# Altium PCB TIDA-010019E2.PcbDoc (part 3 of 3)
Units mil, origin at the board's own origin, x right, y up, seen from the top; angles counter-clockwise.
Board outline 3159.64 x 4813.18 mil, 2 copper layers (Top Layer, Bottom Layer), stack 62 mil thick; 303 components, 177 nets, 861 pads, 1443 vias.
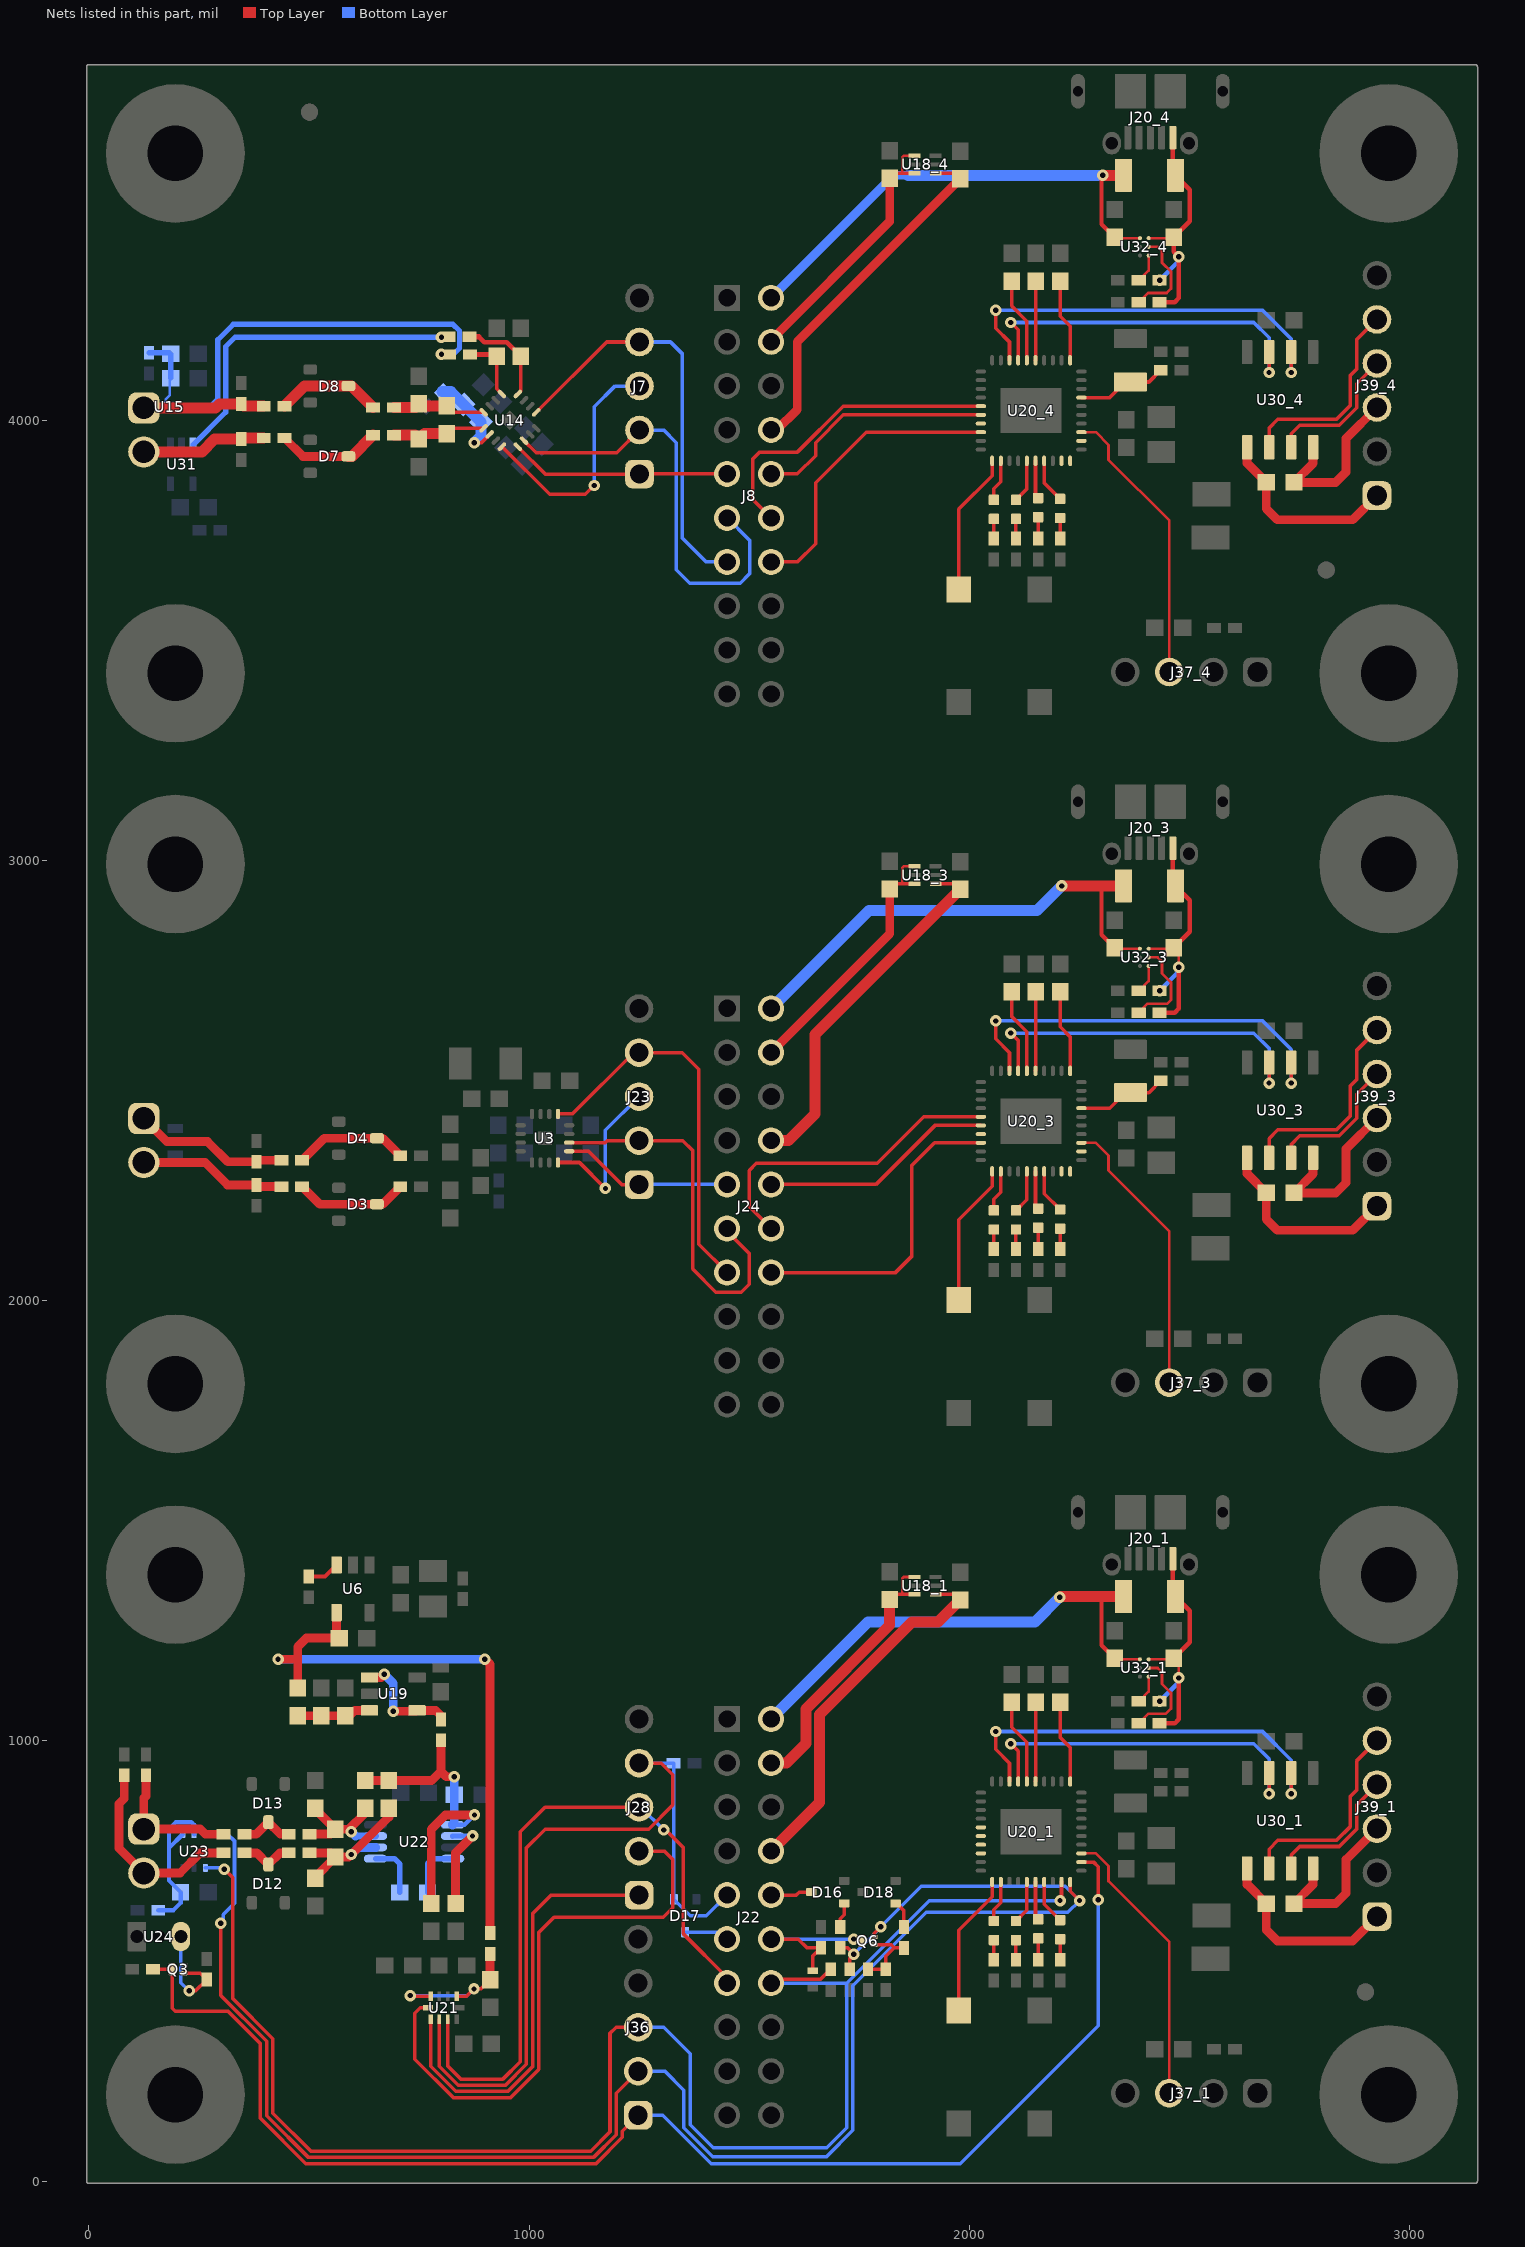
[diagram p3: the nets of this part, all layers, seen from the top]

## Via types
v1: diameter 28, hole 12, Top Layer to Bottom Layer, tented both sides, 1305 vias
v2: diameter 26, hole 12, Top Layer to Bottom Layer, tented both sides, 120 vias
v3: diameter 19.68, hole 7.87, Top Layer to Bottom Layer, tented both sides, 17 vias
v4: diameter 26, hole 12, Top Layer to Bottom Layer, 1 vias

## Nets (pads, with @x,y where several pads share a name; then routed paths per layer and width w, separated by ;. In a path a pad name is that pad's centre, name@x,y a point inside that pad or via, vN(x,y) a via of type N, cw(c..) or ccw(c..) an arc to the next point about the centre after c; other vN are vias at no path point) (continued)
NetC23_3_1: C23_3.1 U20_3.7 Y1_3.1 | length 206
  Top Layer w8: U20_3.7@2254.88,2437.64 2318.89,2437.64 2354.18,2472.93 Y1_3.1@2366.22,2472.93 2408.28,2472.93 C23_3.1@2435.12,2499.77
NetC23_4_1: C23_4.1 U20_4.7 Y1_4.1 | length 206
  Top Layer w8: U20_4.7@2254.88,4051.81 2318.88,4051.81 2354.17,4087.1 Y1_4.1@2366.21,4087.1 2408.27,4087.1 C23_4.1@2435.11,4113.94
NetC34_1_1: C34_1.1 F1_1.2 J20_1.1 R116_1.2 R117_1.2 U32_1.A2 | length 556.1
  Top Layer w6: U32_1.A2@2407.56,1185.53 C34_1.1@2462.47,1185.53 ; C34_1.1@2464.55,1187.61 2476.22,1175.94 v2(2476.22,1143.21)
  Top Layer w10: R116_1.2@2432.65,1040 2466.61,1040 2476.22,1049.61 v2(2476.22,1143.21) ; F1_1.2@2462.68,1334.2 J20_1.1@2462.68,1414.06 ; C34_1.1@2464.55,1187.61 2501.11,1224.17 2501.11,1295.77 F1_1.2@2468.58,1328.3
  Bottom Layer w10: v2(2432.65,1090) v2@2476.22,1133.57
NetC34_3_1: C34_3.1 F1_3.2 J20_3.1 R116_3.2 R117_3.2 U32_3.A2 | length 556.1
  Top Layer w6: U32_3.A2@2407.56,2799.7 C34_3.1@2462.47,2799.7 ; C34_3.1@2464.55,2801.78 2476.22,2790.11 v2(2476.22,2757.38)
  Top Layer w10: R116_3.2@2432.65,2654.17 2466.61,2654.17 2476.22,2663.78 v2(2476.22,2757.38) ; F1_3.2@2462.68,2948.37 J20_3.1@2462.68,3028.24 ; C34_3.1@2464.55,2801.78 2501.11,2838.34 2501.11,2909.94 F1_3.2@2468.58,2942.47
  Bottom Layer w10: v2(2432.65,2704.17) v2@2476.22,2747.74
NetC34_4_1: C34_4.1 F1_4.2 J20_4.1 R116_4.2 R117_4.2 U32_4.A2 | length 577
  Top Layer w6: U32_4.A2@2407.55,4413.87 2462.46,4413.87 C34_4.1@2464.54,4415.95
  Top Layer w10: R116_4.2@2432.65,4268.34 2466.61,4268.34 2476.21,4277.95 v2(2476.21,4371.55) 2464.54,4383.22 C34_4.1@2464.54,4415.95 2501.1,4452.51 2501.1,4524.11 F1_4.2@2468.58,4556.64 2462.67,4562.54 J20_4.1@2462.67,4642.4
  Bottom Layer w10: v2(2432.65,4318.34) 2476.21,4361.91 v2(2476.21,4371.55)
NetC37_1: C37.1 C42.1 R47.1 U14.9 | length 217.6
  Top Layer w8: C42.1@813.43,3969.85 825.48,3981.9 U14.9@896.79,3981.9
  Top Layer w25: R47.1@692.9,3966.39 741.15,3966.39 C37.1@749.99,3957.54 762.29,3969.85 C42.1@813.43,3969.85
NetC40_1: C40.1 C41.1 R44.1 U14.10 | length 212.8
  Top Layer w8: v2(875.79,3949.36) 892.09,3949.36 U14.10@910.71,3967.99
  Bottom Layer w25: R44.1@802.86,4065.04 822.74,4065.04 C41.1@891.1,3996.67 891.1,3964.67 v2(875.79,3949.36)
NetC42_2: C42.2 C43.1 R49.1 U14.8 | length 211.5
  Top Layer w8: C42.2@813.43,4032.84 828.17,4018.1 U14.8@896.79,4018.1
  Top Layer w25: R49.1@692.9,4029.23 741.85,4029.23 745.46,4032.84 C42.2@813.43,4032.84
NetC44_1: C44.1 C45.1 R50.1 U15.A2 U15.B2 | length 182.9
  Bottom Layer w6: U15.B2@175.02,4022.79 U15.A2@175.02,4038.54 175.02,4048.19 183.51,4056.68 183.51,4093.63 C45.1@186.02,4096.13
  Bottom Layer w12: R50.1@136.85,4153.51 183.43,4153.51 C44.1@186.02,4150.92 C45.1@186.02,4096.13
NetC46_1: C46.1 R52.1 U14.5 | length 153.9
  Top Layer w8: C46.1@926.81,4145.99 926.59,4145.77 926.59,4071.81 U14.5@938.55,4059.85
  Top Layer w12: R52.1@865.59,4149.63 923.17,4149.63 C46.1@926.81,4145.99
NetC53_1: C53.1 R8.1 R72.2 U19.3 | length 167.7
  Top Layer w20: R8.1@474.83,1057.29 C53.1@582.92,1057.29 591.78,1057.29 603.95,1069.47 U19.3@637.52,1069.47
NetC67_1: C67.1 R70.1 U21.1 U21.4 | length 347.1
  Top Layer w8: v2(730.54,421.63) 731.52,420.65 U21.4@776.51,420.65 ; U21.1@835.56,420.65 858.98,420.65 v2(875.09,436.76) 890.38,436.76 C67.1@911.54,457.91
  Top Layer w20: C67.1@911.54,457.91 R70.1@911.54,516.37
  Bottom Layer w8: v2(730.54,421.63) 859.97,421.63 v2(875.09,436.76)
NetC69_2: C69.2 C70.1 R74.1 R77.1 U22.2 | length 370.3
  Top Layer w20: R77.1@501.53,745.83 550.56,745.83 C70.1@560,736.39 ; C69.2@514.06,688.28 514.06,690.45 C70.1@560,736.39 ; R74.1@681.81,847.24 681.81,827.6 v2(596.33,742.13) 590.6,736.39 C70.1@560,736.39
  Bottom Layer w20: v2(596.33,742.13) 612.53,758.32 U22.2@651.21,758.32
NetC70_2: C70.2 C73.1 R75.1 R82.1 U22.3 | length 282.9
  Top Layer w20: R82.1@501.53,788.39 549,788.39 C70.2@560,799.38 ; C73.1@514.06,847.24 514.06,845.32 C70.2@560,799.38 ; R75.1@628,847.24 628,836.49 590.89,799.38 C70.2@560,799.38
  Bottom Layer w16: 605.95,784.32 U22.3@651.21,784.32
  Bottom Layer w20: v2(596.33,793.94) 605.95,784.32
NetC72_1: C72.1 R71.1 R74.2 R75.2 R80.1 U22.5 | length 729.7
  Top Layer w20: R75.2@628,910.23 R74.2@681.81,910.23 779.17,910.23 800,931.07 ; R80.1@778,630.81 778,799.52 810.56,832.08 v2(876.15,832.08) ; R71.1@800,993.94 800,931.07 ; v2(830.24,918.7) 812.37,918.7 800,931.07
  Bottom Layer w10: U22.5@826.41,809.51 853.57,809.51 v2(876.15,832.08)
  Bottom Layer w20: U22.5@826.41,809.51 825.72,810.19 830.24,814.71 C72.1@830.24,877.53 v2(830.24,918.7)
NetC74_1: C74.1 R85.2 U23.4 U23.5 | length 368.4
  Bottom Layer w10: R85.2@157.78,615.83 192.31,615.83 208.5,632.02 C74.1@208.5,656.78 182.09,683.2 182.09,756.81 ; U23.4@213.66,788.39 182.09,756.81 ; U23.5@239.25,788.39 239.25,809.44 232.87,815.83 197.91,815.83 182.09,800 182.09,756.81
NetC83_1_1: C83_1.1 J22.4 U18_1.4 U18_1.6 | length 630.9
  Top Layer w6: 1846.22,1333.22 1847.99,1334.99 1847.99,1369.38 1851.2,1372.59 U18_1.4@1875.83,1372.59
  Top Layer w8: C83_1.1@1819.45,1321.41 1831.26,1333.22 1846.22,1333.22 U18_1.6@1875.83,1333.22
  Top Layer w25: J22.4@1550,950 1585.06,950 1629,993.94 1629,1072.84 1819.45,1263.29 C83_1.1@1819.45,1321.41
NetC83_3_1: C83_3.1 J24.4 U18_3.4 U18_3.6 | length 610.3
  Top Layer w6: 1846.22,2947.39 1847.99,2949.16 1847.99,2983.55 1851.2,2986.76 U18_3.4@1875.83,2986.76
  Top Layer w8: C83_3.1@1819.45,2935.58 1831.26,2947.39 1846.22,2947.39 U18_3.6@1875.83,2947.39
  Top Layer w20: J24.4@1550,2564.17 1819.45,2833.62 C83_3.1@1819.45,2935.58
NetC83_4_1: C83_4.1 J8.4 U18_4.4 U18_4.6 | length 610.3
  Top Layer w6: 1846.21,4561.56 1847.99,4563.33 1847.99,4597.72 1851.19,4600.93 U18_4.4@1875.82,4600.93
  Top Layer w8: C83_4.1@1819.44,4549.75 1831.25,4561.56 1846.21,4561.56 U18_4.6@1875.82,4561.56
  Top Layer w20: v4(1550,4182.5) 1819.44,4451.95 C83_4.1@1819.44,4549.75
  Bottom Layer w20: J8.4@1550,4178.35 v4(1550,4182.5)
NetC84_1_1: C84_1.1 J22.8 U18_1.1 | length 843.8
  Top Layer w8: U18_1.1@1923.86,1333.22 1966.54,1333.22 C84_1.1@1979.45,1320.31
  Top Layer w25: J22.8@1550,750 1660,860 1660,1060 1870,1270 1929.14,1270 C84_1.1@1979.45,1320.31
NetC84_3_1: C84_3.1 J24.8 U18_3.1 | length 832.4
  Top Layer w8: U18_3.1@1923.86,2947.39 1966.54,2947.39 C84_3.1@1979.45,2934.48
  Top Layer w25: J24.8@1550,2364.17 1589.81,2364.17 1650,2424.37 1650,2605.03 C84_3.1@1979.45,2934.48
NetC84_4_1: C84_4.1 J8.8 U18_4.1 | length 816.8
  Top Layer w8: U18_4.1@1923.85,4561.56 1966.53,4561.56 C84_4.1@1979.44,4548.65
  Top Layer w20: J8.8@1563.19,3978.35 1609.14,4024.3 1609.14,4178.35 C84_4.1@1979.44,4548.65
  Top Layer w25: J8.8@1550,3978.35 J8.8@1563.19,3978.35
NetC85_1_1: C85_1.1 J39_1.1 U30_1.5 | length 442.3
  Top Layer w20: U30_1.5@2631.22,710.54 2631.22,674.3 C85_1.1@2674.72,630.8 2674.72,570.87 2699.7,545.9 2871.23,545.9 J39_1.1@2926.22,600.89
NetC85_1_2: C85_1.2 J39_1.3 U30_1.8 | length 401.4
  Top Layer w20: U30_1.8@2781.22,710.54 2781.22,674.3 C85_1.2@2737.72,630.8 2832.38,630.8 2856.22,654.64 2856.22,730.89 J39_1.3@2926.22,800.89
NetC85_3_1: C85_3.1 J39_3.1 U30_3.5 | length 442.3
  Top Layer w20: U30_3.5@2631.22,2324.71 2631.22,2288.48 C85_3.1@2674.72,2244.97 2674.72,2185.05 2699.7,2160.07 2871.23,2160.07 J39_3.1@2926.22,2215.06
NetC85_3_2: C85_3.2 J39_3.3 U30_3.8 | length 401.4
  Top Layer w20: U30_3.8@2781.22,2324.71 2781.22,2288.48 C85_3.2@2737.72,2244.97 2832.38,2244.97 2856.22,2268.82 2856.22,2345.06 J39_3.3@2926.22,2415.06
NetC85_4_1: C85_4.1 J39_4.1 U30_4.5 | length 442.3
  Top Layer w20: U30_4.5@2631.21,3938.88 2631.21,3902.65 C85_4.1@2674.72,3859.14 2674.72,3799.22 2699.69,3774.24 2871.22,3774.24 J39_4.1@2926.21,3829.23
NetC85_4_2: C85_4.2 J39_4.3 U30_4.8 | length 401.4
  Top Layer w20: U30_4.8@2781.21,3938.88 2781.21,3902.65 C85_4.2@2737.71,3859.14 2832.37,3859.14 2856.21,3882.98 2856.21,3959.23 J39_4.3@2926.21,4029.23
NetC87_2: C87.2 Q6.1 R110.1 R115.2 | length 168.4
  Top Layer w8: R110.1@1770,481.54 C87.2@1810.76,481.54 1810.76,511.04 1829.87,530.15 ; Q6.1@1783.52,537.04 1822.98,537.04 1829.87,530.15 ; R115.2@1851.76,530.15 1829.87,530.15
NetC88_1: C88.1 J22.12 Q6.3 R84.1 | length 369
  Top Layer w8: J22.12@1550,550 1611.72,550 1631.4,530.32 C88.1@1663.35,530.32 1645,511.97 R84.1@1645,477.91
  Bottom Layer w8: J22.12@1550,550 v2(1737.46,550)
NetC89_1_1: C89_1.1 F1_1.1 J22.2 U32_1.A1 | length 1125.9
  Top Layer w6: C89_1.1@2332.36,1185.53 U32_1.A1@2387.87,1185.53
  Top Layer w10: 2304.51,1328.3 2300.58,1324.36 2300.58,1217.31 C89_1.1@2330.28,1187.61
  Top Layer w25: v2(2205.5,1326.49) 2207.31,1328.3 2304.51,1328.3 F1_1.1@2350.47,1328.3
  Bottom Layer w25: J22.2@1550,1050 1770,1270 2149.01,1270 v2(2205.5,1326.49)
NetC89_3_1: C89_3.1 F1_3.1 J24.2 U32_3.A1 | length 1124.5
  Top Layer w6: C89_3.1@2332.36,2799.7 U32_3.A1@2387.87,2799.7
  Top Layer w10: 2300,2942.47 2300.58,2941.89 2300.58,2831.48 C89_3.1@2330.28,2801.78
  Top Layer w25: v2(2210,2942.46) 2300,2942.47 F1_3.1@2350.47,2942.47
  Bottom Layer w25: J24.2@1550,2664.17 1772.49,2886.67 2154.2,2886.67 v2(2210,2942.46)
NetC89_4_1: C89_4.1 F1_4.1 J8.2 U32_4.A1 | length 1134.7
  Top Layer w6: C89_4.1@2330.28,4415.95 2332.36,4413.87 U32_4.A1@2387.87,4413.87
  Top Layer w10: v2(2303.59,4556.64) 2300.57,4553.62 2300.57,4445.65 C89_4.1@2330.28,4415.95
  Top Layer w25: v2(2303.59,4556.64) 2339.35,4556.64 F1_4.1@2351.68,4544.31
  Bottom Layer w20: J8.2@1550,4278.35 1828.29,4556.64 1861.02,4556.64
  Bottom Layer w25: 1861.02,4556.64 v2(2303.59,4556.64)
NetC90_1: C90.1 R121.1 U14.4 | length 223.3
  Top Layer w8: U14.4@974.74,4059.85 981.02,4066.14 C90.1@981.02,4145.99
  Top Layer w10: 885.75,4190 898.27,4177.48 949.53,4177.48 C90.1@981.02,4145.99
  Top Layer w12: R121.1@864.65,4190 885.75,4190
NetD1_1_1: D1_1.1 R27_1.2 | length 46.6
  Top Layer w8: R27_1.2@2206.46,503.19 D1_1.1@2206.46,549.83
NetD1_1_2: D1_1.2 U20_1.37 | length 101.6
  Top Layer w8: U20_1.37@2170.24,679.77 2170.24,629.36 D1_1.2@2206.46,593.14
NetD1_3_1: D1_3.1 R27_3.2 | length 46.6
  Top Layer w8: R27_3.2@2206.46,2117.36 D1_3.1@2206.46,2164.01
NetD1_3_2: D1_3.2 U20_3.37 | length 101.6
  Top Layer w8: U20_3.37@2170.24,2293.94 2170.24,2243.54 D1_3.2@2206.46,2207.32
NetD1_4_1: D1_4.1 R27_4.2 | length 46.6
  Top Layer w8: R27_4.2@2206.45,3731.53 D1_4.1@2206.45,3778.18
NetD1_4_2: D1_4.2 U20_4.37 | length 101.6
  Top Layer w8: U20_4.37@2170.23,3908.11 2170.23,3857.7 D1_4.2@2206.45,3821.48
NetD2_1_1: D2_1.1 R55_1.2 | length 48.6
  Top Layer w8: R55_1.2@2156.46,503.19 D2_1.1@2156.46,551.8
NetD2_1_2: D2_1.2 U20_1.36 | length 87.1
  Top Layer w8: U20_1.36@2150.55,679.77 2150.55,601.02 D2_1.2@2156.46,595.11
NetD2_3_1: D2_3.1 R55_3.2 | length 48.6
  Top Layer w8: R55_3.2@2156.46,2117.36 D2_3.1@2156.46,2165.98
NetD2_3_2: D2_3.2 U20_3.36 | length 87.1
  Top Layer w8: U20_3.36@2150.55,2293.94 2150.55,2215.19 D2_3.2@2156.46,2209.28
NetD2_4_1: D2_4.1 R55_4.2 | length 48.6
  Top Layer w8: R55_4.2@2156.45,3731.53 D2_4.1@2156.45,3780.15
NetD2_4_2: D2_4.2 U20_4.36 | length 87.1
  Top Layer w8: U20_4.36@2150.54,3908.11 2150.54,3829.36 D2_4.2@2156.45,3823.45
NetD3_3: D3.3 R11.1 R12.2 | length 255.9
  Top Layer w20: R11.1@484.68,2259.41 524.68,2219.41 D3.3@654.37,2219.41 667.44,2219.41 R12.2@707.44,2259.41
NetD4_3: D4.3 R13.1 R14.2 | length 260
  Top Layer w20: R13.1@484.68,2319.41 534.68,2369.41 D4.3@654.37,2369.41 667.44,2369.41 R14.2@707.44,2329.41
NetD7_3: D7.3 R46.1 R47.2 | length 238.3
  Top Layer w20: R46.1@444.65,3960 486.49,3918.16 D7.3@589.72,3918.16
  Top Layer w25: D7.3@589.72,3918.16 597.43,3918.16 R47.2@645.66,3966.39
NetD8_3: D8.3 R48.1 R49.2 | length 240.4
  Top Layer w25: R48.1@444.65,4032.13 444.65,4032.4 490.25,4078 D8.3@589.72,4078 596.89,4078 R49.2@645.66,4029.23
NetD9_1_1: D9_1.1 R56_1.2 | length 44.5
  Top Layer w8: R56_1.2@2106.22,503.19 D9_1.1@2106.22,547.72
NetD9_1_2: D9_1.2 U20_1.35 | length 98.9
  Top Layer w8: D9_1.2@2106.22,591.03 2130.87,615.68 U20_1.35@2130.87,679.77
NetD9_3_1: D9_3.1 R56_3.2 | length 44.5
  Top Layer w8: R56_3.2@2106.22,2117.36 D9_3.1@2106.22,2161.9
NetD9_3_2: D9_3.2 U20_3.35 | length 98.9
  Top Layer w8: D9_3.2@2106.22,2205.2 2130.87,2229.85 U20_3.35@2130.87,2293.94
NetD9_4_1: D9_4.1 R56_4.2 | length 44.5
  Top Layer w8: R56_4.2@2106.21,3731.53 D9_4.1@2106.21,3776.07
NetD9_4_2: D9_4.2 U20_4.35 | length 98.9
  Top Layer w8: D9_4.2@2106.21,3819.37 2130.86,3844.02 U20_4.35@2130.86,3908.11
NetD10_1_1: D10_1.1 R57_1.2 | length 44.5
  Top Layer w8: R57_1.2@2056.06,503.19 D10_1.1@2056.06,547.72
NetD10_1_2: D10_1.2 U20_1.32 | length 95.3
  Top Layer w8: D10_1.2@2056.06,591.03 2056.06,616.56 2071.81,632.31 U20_1.32@2071.81,679.77
NetD10_3_1: D10_3.1 R57_3.2 | length 44.5
  Top Layer w8: R57_3.2@2056.06,2117.36 D10_3.1@2056.06,2161.9
NetD10_3_2: D10_3.2 U20_3.32 | length 95.3
  Top Layer w8: D10_3.2@2056.06,2205.2 2056.06,2230.73 2071.81,2246.48 U20_3.32@2071.81,2293.94
NetD10_4_1: D10_4.1 R57_4.2 | length 44.5
  Top Layer w8: R57_4.2@2056.06,3731.53 D10_4.1@2056.06,3776.07
NetD10_4_2: D10_4.2 U20_4.32 | length 95.3
  Top Layer w8: D10_4.2@2056.06,3819.37 2056.06,3844.9 2071.8,3860.65 U20_4.32@2071.8,3908.11
NetD12_3: D12.3 R76.1 R77.2 | length 122.6
  Top Layer w20: R76.1@353.62,745.83 381.46,745.83 D12.3@408,719.29 434.54,745.83 R77.2@454.29,745.83
NetD13_3: D13.3 R81.1 R82.2 | length 123.5
  Top Layer w20: R81.1@353.62,787.99 380.25,787.99 D13.3@408,815.74 435.36,788.39 R82.2@454.29,788.39
NetD16_1: D16.1 R114.1 | length 57.5
  Top Layer w8: R114.1@1706.65,577.57 1706.65,595.86 1716.24,605.45 D16.1@1716.24,631.14
NetD16_3: D16.3 J22.10 | length 94.2
  Top Layer w8: J22.10@1550,650 1607.1,650 1613.83,656.73 D16.3@1641.44,656.73
NetD18_1: D18.1 R115.1 | length 63.2
  Top Layer w8: D18.1@1832.67,631.14 1835.23,631.14 1851.76,614.61 R115.1@1851.76,577.39
NetJ2_1: J2.1 R13.2 R15.2 | length 354.7
  Top Layer w20: J2.1@125,2414.17 177.63,2361.55 269.67,2361.55 315.43,2315.78 R15.2@381.06,2315.78 384.68,2319.41 R13.2@437.44,2319.41
NetJ2_2: J2.2 R10.1 R11.2 | length 335.1
  Top Layer w20: J2.2@125,2314.17 264.14,2314.17 315.29,2263.03 R10.1@381.06,2263.03 384.68,2259.41 R11.2@437.44,2259.41
NetJ5_1: J5.1 R48.2 R51.2 | length 278.3
  Top Layer w25: J5.1@124.99,4028.35 287.55,4028.35 296.56,4037.36 R51.2@346.01,4037.36 351.24,4032.13 R48.2@397.4,4032.13
NetJ5_2: J5.2 R45.1 R46.2 | length 285.5
  Top Layer w25: J5.2@124.99,3928.35 256.85,3928.35 285.83,3957.33 R45.1@346.01,3957.33 348.69,3960 R46.2@397.4,3960
NetJ7_1: J7.1 J8.9 U14.13 | length 501.1
  Top Layer w8: U14.13@974.74,3940.15 1036.89,3878 J7.1@1251.02,3878 1251.37,3878.35 J8.9@1450,3878.35
NetJ7_2: J7.2 J8.11 U14.14 | length 1015.9
  Top Layer w8: U14.14@988.66,3954.07 1016.68,3926.05 1199.07,3926.05 J7.2@1251.02,3978
  Bottom Layer w8: J7.2@1251.02,3978 1305.98,3978 1334.52,3949.45 1334.52,3660.42 1364.95,3630 1479.6,3630 1501.02,3651.42 1501.02,3727.32 J8.11@1450,3778.35
NetJ7_3: J7.3 U14.12 | length 563.9
  Top Layer w8: U14.12@938.55,3940.15 1046.75,3831.95 1128.07,3831.95 v2(1148.09,3851.97)
  Bottom Layer w8: v2(1148.09,3851.97) 1148.09,4030.64 1195.45,4078 J7.3@1251.02,4078
NetJ7_4: J7.4 J8.13 U14.1 | length 951.8
  Top Layer w8: U14.1@1016.5,4018.1 1176.4,4178 J7.4@1251.02,4178
  Bottom Layer w8: J7.4@1251.02,4178 1321.37,4178 1348.52,4150.85 1348.52,3732.5 1402.68,3678.35 J8.13@1450,3678.35
NetJ8_10: J8.10 U20_4.26 | length 549.3
  Top Layer w8: J8.10@1550,3878.35 1609.37,3878.35 1651.02,3920 1651.02,3949.43 1714.03,4012.44 U20_4.26@2026.53,4012.44
NetJ8_12: J8.12 U20_4.25 | length 719.4
  Top Layer w8: J8.12@1550,3778.35 1508.12,3820.23 1508.12,3912.31 1523.81,3928 1609.79,3928 1713.92,4032.12 U20_4.25@2026.53,4032.12
NetJ8_14: J8.14 U20_4.28 | length 679.6
  Top Layer w8: J8.14@1550,3678.35 1609.37,3678.35 1651.02,3720 1651.02,3858.34 1765.75,3973.07 U20_4.28@2026.53,3973.07
NetJ22_14: J22.14 J36.3 R112.1 U20_1.39 U23.1 | length 3712.6
  Top Layer w8: v2(308,708.66) 326.83,689.83 326.83,414.98 418,323.8 418,154.74 504.74,68 1140,68 1184,112 1184,335.83 1198,349.83 J36.3@1248,349.83 ; J22.14@1550,450 1559.27,459.27 1662.74,459.27 R112.1@1685,481.54 ; v2(2206.46,637.44) 2209.61,640.59 U20_1.39@2209.61,679.77
  Bottom Layer w8: U23.1@264.84,711.61 305.05,711.61 v2(308,708.66) ; J36.3@1248,349.83 1306,349.83 1365.91,289.92 1365.91,128.54 1418.62,75.83 1676.03,75.83 1721.76,121.56 1721.76,450 ; J22.14@1550,450 1721.76,450 ; v2(2206.46,637.44) 1909.2,637.44 1721.76,450
NetJ23_1: J23.1 J24.9 U3.13 | length 390.3
  Top Layer w8: U3.13@1091.3,2339.72 1135.23,2339.72 1211.12,2263.83 J23.1@1250,2263.83
  Bottom Layer w8: J23.1@1250,2263.83 1250.35,2264.17 J24.9@1450,2264.17
NetJ23_2: J23.2 J24.11 U3.14 | length 865.4
  Top Layer w8: U3.14@1091.3,2359.41 1173.58,2359.41 1178,2363.83 J23.2@1250,2363.83 1349.2,2363.83 1371.59,2341.44 1371.59,2072.24 1424.22,2019.61 1481.82,2019.61 1500,2037.8 1500,2107.52 1450,2157.52 J24.11@1450,2164.17
NetJ23_3: J23.3 U3.12 | length 372.7
  Top Layer w8: U3.12@1065.71,2314.13 1114.57,2314.13 v2(1173.58,2255.12)
  Bottom Layer w8: v2(1173.58,2255.12) 1173.58,2387.41 J23.3@1250,2463.83
NetJ23_4: J23.4 J24.13 U3.1 | length 882
  Top Layer w8: U3.1@1065.71,2424.37 1098.54,2424.37 1238,2563.83 J23.4@1250,2563.83 1348,2563.83 1385.59,2526.23 1385.59,2128.58 J24.13@1450,2064.17
NetJ24_10: J24.10 U20_3.26 | length 532.1
  Top Layer w8: J24.10@1550,2264.17 1788.15,2264.17 1922.25,2398.27 U20_3.26@2026.54,2398.27
NetJ24_12: J24.12 U20_3.25 | length 729.5
  Top Layer w8: J24.12@1550,2164.17 1500,2214.17 1500,2295.83 1516.51,2312.33 1790.94,2312.33 1896.56,2417.96 U20_3.25@2026.54,2417.96
NetJ24_14: J24.14 U20_3.28 | length 719.4
  Top Layer w8: J24.14@1550,2064.17 1832.67,2064.17 1868.94,2100.44 1868.94,2306.61 1921.22,2358.9 U20_3.28@2026.54,2358.9
NetJ28_1: J28.1 U21.6 | length 992
  Top Layer w8: U21.6@776.51,367.5 776.51,261.3 833.73,204.08 952.39,204.08 1008,259.69 1008,607.95 1049.88,649.83 J28.1@1250,649.83
NetJ28_2: J28.2 U21.5 | length 1316.3
  Top Layer w8: U21.5@770.11,394.07 753.04,394.07 740.72,381.76 740.72,277.29 827.93,190.08 958.19,190.08 1022,253.89 1022,564.95 1056.89,599.83 1305.22,599.83 1326.91,621.52 1326.91,730.84 1307.92,749.83 J28.2@1250,749.83
NetJ31_1: J31.1 R81.2 R83.2 | length 310.6
  Top Layer w20: R83.2@130,922.2 130,875.18 125,870.18 J31.1@125,800 253.23,800 265.24,787.99 R81.2@306.38,787.99
NetJ31_2: J31.2 R73.1 R76.2 | length 450.8
  Top Layer w20: R73.1@80.41,922.2 80.41,869.47 68.6,857.66 68.6,756.39 J31.2@125,700 207.12,700 252.95,745.83 R76.2@306.38,745.83
NetJ36_1: J36.1 Q3.3 R86.1 U20_1.2 | length 3111.4
  Top Layer w8: R86.1@148.62,481.54 Q3.3@189.35,481.54 189.35,393.02 196.55,385.83 316.38,385.83 390,312.2 390,143.14 493.14,40 1152.17,40 1212,99.83 1212,113.83 J36.1@1248,149.83 ; U20_1.2@2254.88,725.04 2282.34,725.04 2293.39,713.99 v2(2293.39,639.2)
  Bottom Layer w8: J36.1@1248,149.83 1303.9,149.83 1337.91,115.82 1337.91,115.49 1411.56,41.83 1411.9,41.83 1413.72,40 1980,40 2293.39,353.39 v2(2293.39,639.2)
NetJ36_2: J36.2 Q6.2 R111.1 R114.2 U20_1.40 U23.6 | length 4088.6
  Top Layer w8: v2(300,585.83) 300,422 404,318 404,148.94 498.94,54 1146.37,54 1198,105.63 1198,199.83 J36.2@1248,249.83 ; R114.2@1706.65,530.32 1723.48,530.32 v2(1737.97,515.83) 1728.55,506.4 R111.1@1728.55,481.54 ; Q6.2@1784.18,554.58 1784.18,563.34 v2(1798.95,578.1) ; U20_1.40@2229.29,679.77 2229.29,658.83 v2(2250.68,637.44)
  Bottom Layer w8: U23.6@264.84,788.39 315.44,788.39 331,772.83 331,631.78 305.05,605.83 305.05,585.83 v2(300,585.83) ; J36.2@1248,249.83 1308.91,249.83 1351.91,206.83 1351.91,121.29 1417.36,55.83 1675.83,55.83 1735.76,115.76 1735.76,444.2 1902.41,610.86 2224.09,610.86 v2(2250.68,637.44) 2218.12,670 1890.84,670 v2(1798.95,578.1) 1798.95,576.8 v2(1737.97,515.83)
NetJ37_1_3: J37_1.3 U20_1.3 | length 646.6
  Top Layer w6: U20_1.3@2254.88,744.73 2287.56,744.73 2316.52,715.77 2316.52,681.62 2454.51,543.63 J37_1.3@2454.51,200
NetJ37_3_3: J37_3.3 U20_3.3 | length 646.6
  Top Layer w6: U20_3.3@2254.88,2358.9 2287.56,2358.9 2316.52,2329.94 2316.52,2295.8 2454.51,2157.8 J37_3.3@2454.51,1814.17
NetJ37_4_3: J37_4.3 U20_4.3 | length 646.6
  Top Layer w6: U20_4.3@2254.88,3973.07 2287.55,3973.07 2316.51,3944.11 2316.51,3909.97 2454.51,3771.97 J37_4.3@2454.51,3428.34
NetJ39_1_4: J39_1.4 U30_1.7 | length 352.2
  Top Layer w8: U30_1.7@2731.22,710.54 2731.22,740.93 2750.59,760.31 2840.23,760.31 2880,800.08 2880,854.67 J39_1.4@2926.22,900.89 J39_1.4@2897.67,900.89
NetJ39_1_5: J39_1.5 U30_1.6 | length 486.7
  Top Layer w8: U30_1.6@2681.22,710.54 2681.22,754.38 2701.15,774.31 2834.43,774.31 2866,805.87 2866,874.31 2879.84,888.15 2879.84,954.51 J39_1.5@2926.22,1000.89 J39_1.5@2909.47,1000.89
NetJ39_3_4: J39_3.4 U30_3.7 | length 352.2
  Top Layer w8: U30_3.7@2731.22,2324.71 2731.22,2355.11 2750.59,2374.48 2840.23,2374.48 2880,2414.25 2880,2468.84 J39_3.4@2926.22,2515.06 J39_3.4@2897.67,2515.06
NetJ39_3_5: J39_3.5 U30_3.6 | length 486.7
  Top Layer w8: U30_3.6@2681.22,2324.71 2681.22,2368.55 2701.15,2388.48 2834.43,2388.48 2866,2420.05 2866,2488.48 2879.84,2502.32 2879.84,2568.68 J39_3.5@2926.22,2615.06 J39_3.5@2909.47,2615.06
NetJ39_4_4: J39_4.4 U30_4.7 | length 352.2
  Top Layer w8: U30_4.7@2731.21,3938.88 2731.21,3969.28 2750.59,3988.65 2840.22,3988.65 2879.99,4028.42 2879.99,4083.01 J39_4.4@2926.21,4129.23 J39_4.4@2897.67,4129.23
NetJ39_4_5: J39_4.5 U30_4.6 | length 486.7
  Top Layer w8: U30_4.6@2681.21,3938.88 2681.21,3982.72 2701.14,4002.65 2834.42,4002.65 2865.99,4034.22 2865.99,4102.65 2879.83,4116.49 2879.83,4182.85 J39_4.5@2926.21,4229.23 J39_4.5@2909.47,4229.23
NetQ3_1: Q3.1 R87.2 U24.2 | length 239.1
  Top Layer w8: Q3.1@216.91,472.68 253.24,472.68 R87.2@268,457.91 242.41,432.32 v2(228,432.32)
  Bottom Layer w8: U24.2@209.15,555.83 209.15,451.17 v2(228,432.32)
NetR6_2: R6.2 U6.3 | length 74.1
  Top Layer w10: R6.2@499.56,1373.73 536.61,1373.73 U6.3@562.83,1399.96
NetR52_2: R52.2 U15.B1 | length 903.6
  Bottom Layer w6: U15.B1@190.77,4022.79 267.3,4022.79
  Bottom Layer w12: 267.3,4022.79 293.02,4048.51 293.02,4182.93 328.25,4218.16 827.26,4218.16 841.97,4203.45 841.97,4163.78 827.82,4149.63 827.45,4150 v2(801.02,4150)
NetR65_1_2: R65_1.2 U20_1.15 | length 180.2
  Top Layer w8: U20_1.15@2150.55,908.11 2151.54,909.1 R65_1.2@2151.54,1087.88
NetR65_3_2: R65_3.2 U20_3.15 | length 180.2
  Top Layer w8: U20_3.15@2150.55,2522.29 2151.54,2523.27 R65_3.2@2151.54,2702.06
NetR65_4_2: R65_4.2 U20_4.15 | length 180.2
  Top Layer w8: U20_4.15@2150.54,4136.46 2151.53,4137.44 R65_4.2@2151.53,4316.22
NetR66_1_2: R66_1.2 U20_1.16 | length 194.1
  Top Layer w8: R66_1.2@2096.38,1087.88 2096.38,1031.54 2130.87,997.06 U20_1.16@2130.87,908.11
NetR66_3_2: R66_3.2 U20_3.16 | length 194.1
  Top Layer w8: R66_3.2@2096.38,2702.06 2096.38,2645.72 2130.87,2611.23 U20_3.16@2130.87,2522.29
NetR66_4_2: R66_4.2 U20_4.16 | length 194.1
  Top Layer w8: R66_4.2@2096.37,4316.22 2096.37,4259.89 2130.86,4225.4 U20_4.16@2130.86,4136.46
NetR71_2: R71.2 U19.1 U19.4 | length 243.8
  Top Layer w20: U19.1@637.52,1144.27 663.7,1144.27 v2(671.1,1151.67) ; v2(691.65,1067.44) 743.76,1067.44 U19.4@745.79,1069.47 787.47,1069.47 R71.2@800,1056.93
  Bottom Layer w20: v2(671.1,1151.67) 691.65,1131.12 v2(691.65,1067.44)
NetR78_1: R78.1 U22.6 | length 215.1
  Top Layer w20: R78.1@833.23,630.81 833.23,745.72 v2(871.84,784.32)
  Bottom Layer w12: U22.6@826.41,783.92 826.82,784.32 v2(871.84,784.32)
NetR79_1: R79.1 U22.8 | length 127.2
  Bottom Layer w12: R79.1@769.59,655.83 769.59,721.62 780.7,732.73 U22.8@826.41,732.73
NetR79_2: R79.2 U22.1 | length 125.2
  Bottom Layer w12: U22.1@651.21,732.73 694.53,732.73 706.59,720.67 R79.2@706.59,655.83
NetR109_1_2: R109_1.2 U20_1.11 | length 189.2
  Top Layer w8: R109_1.2@2206.46,1087.88 2206.46,1007.94 2229.29,985.11 U20_1.11@2229.29,908.11
NetR109_3_2: R109_3.2 U20_3.11 | length 189.2
  Top Layer w8: R109_3.2@2206.46,2702.06 2206.46,2622.11 2229.29,2599.28 U20_3.11@2229.29,2522.29
NetR109_4_2: R109_4.2 U20_4.11 | length 189.2
  Top Layer w8: R109_4.2@2206.45,4316.22 2206.45,4236.28 2229.28,4213.45 U20_4.11@2229.28,4136.46
NetR116_1_1: R116_1.1 R118_1.2 U32_1.B2 | length 212.9
  Top Layer w6: R118_1.2@2384.65,1040 2406.31,1061.65 2446.37,1061.65 2458.24,1073.52 2458.24,1109.29 2437.87,1129.66 2437.87,1156.22 2428.25,1165.84 U32_1.B2@2407.56,1165.84
NetR116_3_1: R116_3.1 R118_3.2 U32_3.B2 | length 215.5
  Top Layer w6: R118_3.2@2384.65,2654.17 2405.46,2674.98 2449.88,2674.98 2458.24,2683.35 2458.24,2723.46 2437.87,2743.83 2437.87,2770.39 2428.25,2780.02 U32_3.B2@2407.56,2780.02
NetR116_4_1: R116_4.1 R118_4.2 U32_4.B2 | length 213.8
  Top Layer w6: R116_4.1@2385.4,4268.34 2406.21,4289.15 2448.33,4289.15 2458.24,4299.05 2458.24,4337.63 2437.87,4358 2437.87,4384.56 2428.24,4394.18 U32_4.B2@2407.55,4394.18
NetR117_1_1: R117_1.1 R119_1.2 U32_1.C2 | length 65.3
  Top Layer w6: R117_1.1@2385.41,1090 2407.56,1112.15 U32_1.C2@2407.56,1146.16
NetR117_3_1: R117_3.1 R119_3.2 U32_3.C2 | length 65.3
  Top Layer w6: R117_3.1@2385.41,2704.17 2407.56,2726.32 U32_3.C2@2407.56,2760.33
NetR117_4_1: R117_4.1 R119_4.2 U32_4.C2 | length 65.3
  Top Layer w6: R117_4.1@2385.4,4318.34 2407.55,4340.49 U32_4.C2@2407.55,4374.5
NetR121_2: R121.2 U31.3 | length 752.9
  Bottom Layer w12: U31.3@236.61,3944.29 311.02,4018.7 311.02,4167.7 332.02,4188.7 v2(801.02,4188.7)
NetS2_1_2: S2_1.2 U20_1.31 | length 323.9
  Top Layer w8: S2_1.2@1976.22,387.33 1976.22,570.25 2052.13,646.15 U20_1.31@2052.13,679.77
NetS2_3_2: S2_3.2 U20_3.31 | length 323.9
  Top Layer w8: S2_3.2@1976.22,2001.5 1976.22,2184.42 2052.13,2260.32 U20_3.31@2052.13,2293.94
NetS2_4_2: S2_4.2 U20_4.31 | length 323.9
  Top Layer w8: S2_4.2@1976.21,3615.67 1976.21,3798.59 2052.12,3874.49 U20_4.31@2052.12,3908.11
NetU20_1_17: U20_1.17 U30_1.3 | length 819.3
  Top Layer w8: v2(2094.41,993.94) 2111.18,977.17 U20_1.17@2111.18,908.11 ; v2(2681.22,880.41) U30_1.3@2681.22,927.07
  Bottom Layer w8: v2(2094.41,993.94) 2646.22,993.94 2681.22,958.94 v2(2681.22,880.41)
NetU20_1_18: U20_1.18 U30_1.2 | length 947.5
  Top Layer w8: v2(2060,1021.57) 2060,981.14 2091.5,949.65 U20_1.18@2091.5,908.11 ; v2(2731.22,880.41) U30_1.2@2731.22,927.07
  Bottom Layer w8: v2(2060,1021.57) 2666.22,1021.57 2731.22,956.57 v2(2731.22,880.41)
NetU20_1_25: U20_1.25
NetU20_1_26: U20_1.26
NetU20_1_27: U20_1.27
NetU20_1_28: U20_1.28
NetU20_3_2: U20_3.2
NetU20_3_17: U20_3.17 U30_3.3 | length 819.3
  Top Layer w8: v2(2094.41,2608.11) 2111.18,2591.34 U20_3.17@2111.18,2522.29 ; v2(2681.22,2494.58) U30_3.3@2681.22,2541.25
  Bottom Layer w8: v2(2094.41,2608.11) 2646.22,2608.11 2681.22,2573.11 v2(2681.22,2494.58)
NetU20_3_18: U20_3.18 U30_3.2 | length 947.5
  Top Layer w8: v2(2060,2635.74) 2060,2595.32 2091.5,2563.82 U20_3.18@2091.5,2522.29 ; v2(2731.22,2494.58) U30_3.2@2731.22,2541.25
  Bottom Layer w8: v2(2060,2635.74) 2666.22,2635.74 2731.22,2570.74 v2(2731.22,2494.58)
NetU20_3_27: U20_3.27
NetU20_3_39: U20_3.39
NetU20_3_40: U20_3.40
NetU20_4_2: U20_4.2
NetU20_4_17: U20_4.17 U30_4.3 | length 819.3
  Top Layer w8: v2(2094.4,4222.28) 2111.17,4205.51 U20_4.17@2111.17,4136.46 ; v2(2681.21,4108.75) U30_4.3@2681.21,4155.42
  Bottom Layer w8: v2(2094.4,4222.28) 2646.21,4222.28 2681.21,4187.28 v2(2681.21,4108.75)
NetU20_4_18: U20_4.18 U30_4.2 | length 947.5
  Top Layer w8: v2(2059.99,4249.91) 2059.99,4209.49 2091.49,4177.99 U20_4.18@2091.49,4136.46 ; v2(2731.21,4108.75) U30_4.2@2731.21,4155.42
  Bottom Layer w8: v2(2059.99,4249.91) 2666.21,4249.91 2731.21,4184.91 v2(2731.21,4108.75)
NetU20_4_27: U20_4.27
NetU20_4_39: U20_4.39
NetU20_4_40: U20_4.40
SCL_5: J22.13 J28.3 U21.8 | length 1601.6
  Top Layer w8: U21.8@815.88,367.5 815.88,261.53 845.32,232.08 940.8,232.08 980,271.29 980,793.47 1036.36,849.83 J28.3@1250,849.83 ; v2(1306,797.88) 1310.3,797.88 1350.9,757.28 1350.9,561.61 1450,462.51 J22.13@1450,450
  Bottom Layer w8: J28.3@1250,849.83 1254.05,849.83 v2(1306,797.88)
SDA_Rx_5: D17.3 J22.11 | length 101.8
  Bottom Layer w8: D17.3@1354.59,565.54 1434.46,565.54 J22.11@1450,550
SDA_Tx_5: D17.1 J22.9 J28.4 R113.1 U21.7 | length 1906.5
  Top Layer w8: U21.7@796.19,367.5 796.19,261.42 839.52,218.08 946.59,218.08 994,265.49 994,756.93 1036.74,799.68 1271.85,799.68 1326.91,854.73 1326.91,922.92 1300,949.83 J28.4@1250,949.83
  Bottom Layer w8: J28.4@1250,949.83 1250.18,949.65 R113.1@1328.28,949.65 1329,948.93 D17.1@1329,640.35 1366.4,602.94 1402.95,602.94 J22.9@1450,650
Vref_5: C9.1 R8.2 R70.2 U6.4 | length 1398.1
  Top Layer w20: v2(430,1185.83) 474.83,1185.83 ; R8.2@474.83,1120.28 474.83,1185.83 ; U6.4@562.83,1291.69 562.83,1239.53 C9.1@568.74,1233.62 494.18,1233.62 474.83,1214.27 474.83,1185.83 ; v2(899.72,1185.83) 911.54,1174.02 R70.2@911.54,563.61
  Bottom Layer w20: v2(430,1185.83) v2(899.72,1185.83)
pads on no net: D16.2 D17.2 D18.2 FID1.1 FID2.1 FID3.1 FID4.1 FID5.1 FID6.1 H9.1 H10.1 H11.1 H12.1 H13.0 H14.0 H15.0 H16.0 H17.1 H18.1 H19.1 H20.1 H21.0 H22.0 H23.0 H24.0 H37.1 H38.1 H39.1 H40.1 H45.0 H46.0 H47.0 H48.0 J8.1 J8.3 J8.15 J8.16 J8.17 J8.18 J20_1.2 J20_1.3 J20_1.4 J20_3.2 J20_3.3 J20_3.4 J20_4.2 J20_4.3 J20_4.4 J22.1 J22.3 J22.15 J22.16 J22.17 J22.18 J24.1 J24.3 J24.15 J24.16 J24.17 J24.18 J39_1.2 J39_1.6 J39_3.2 J39_3.6 J39_4.2 J39_4.6 LBL1.0 LBL3.0 LBL4.0 SH-J1.0 SH-J2.0 SH-J3.0 SH-J4.0 SH-J5.0 SH-J6.0 SH-J7.0 SH-J8.0 SH-J9.0 SH-J10.0 SH-J11.0 SH-J12.0 SH-J13.0 SH-J14.0 SH-J15.0 SH-J16.0 SH-J17.0 SH-J18.0 SH-J19.0 SH-J20.0 SH-J21.0 U3.15 U3.16 U14.6 U14.7 U14.15 U14.16 U18_1.2 U18_1.5 U18_3.2 U18_3.5 U18_4.2 U18_4.5 U20_1.1 U20_1.9 U20_1.10 U20_1.12 U20_1.13 U20_1.14 U20_1.19 U20_1.20 U20_1.21 U20_1.22 U20_1.23 U20_1.24 U20_1.29 U20_1.30 U20_1.33 U20_1.34 U20_1.38 U20_3.1 U20_3.9 U20_3.10 U20_3.12 U20_3.13 U20_3.14 U20_3.19 U20_3.20 U20_3.21 U20_3.22 U20_3.23 U20_3.24 U20_3.29 U20_3.30 U20_3.33 U20_3.34 U20_3.38 U20_4.1 U20_4.9 U20_4.10 U20_4.12 U20_4.13 U20_4.14 U20_4.19 U20_4.20 U20_4.21 U20_4.22 U20_4.23 U20_4.24 U20_4.29 U20_4.30 U20_4.33 U20_4.34 U20_4.38 U23.3 U24.MH U31.1 U31.5 U32_1.C1 U32_3.C1 U32_4.C1

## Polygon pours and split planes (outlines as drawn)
GND_4 on Top Layer "TOP_LAYER_GND_4_P048" (solid, remove dead copper, pour order 48): 1565.23,4803.15 2757.87,4803.15 2811.02,4750 2811.02,4128.35 2781.02,4098.35 2580.79,4098.35 2580.79,3803.15 2701.02,3682.91 2701.02,3292.74 2636.63,3228.35 1697.87,3228.35 1572.68,3228.35 1511.02,3290 1511.02,4748.94
GND_11 on Top Layer "TOP_LAYER_GND_11_P040" (solid, remove dead copper, pour order 40): 0,4380 2.17,4382.17 1478.19,4382.17 1478.19,3520 0,3520
GND_8 on Top Layer "TOP_LAYER_GND_8_P026" (solid, remove dead copper, pour order 26): 0,2795.83 0.3,2796.12 1401.57,2796.12 1401.57,1990.55 1396.85,1985.83 0,1985.83
GND_7 on Top Layer "TOP_LAYER_GND_7_P024" (solid, remove dead copper, pour order 24): 1140,598.84 1088.44,547.28 1088.44,267.41 986.86,165.83 675.13,165.83 530,310.96 530,500 378.26,651.74 338.26,651.74 301.18,688.82 301.18,728.82 0,728.82 0,896.18 0,1580 5.2,1574.8 1500,1574.8 1500,598.84
GND_3 on Top Layer "TOP_LAYER_GND_3_P018" (solid, remove dead copper, pour order 18): 1625.13,3202.45 2768.73,3202.45 2840,3131.18 2840,2527.65 2810,2497.65 2609.76,2497.65 2609.76,2202.45 2730,2082.21 2730,1687.26 2670.39,1627.65 1726.84,1627.65 1603.52,1627.65 1540,1691.17 1540,3117.32
NetC6_1 on Top Layer "TOP_LAYER_NETC6_1_P016" (solid, remove dead copper, pour order 16): 581.53,1442.01 591.53,1452.01 871.84,1452.01 881.53,1442.31 881.53,1360.35 873.04,1351.86 591.38,1351.86 581.53,1361.7
GND_1 on Top Layer "TOP_LAYER_GND_1_P012" (solid, remove dead copper, pour order 12): 1604.99,1570.63 2793.33,1570.63 2840,1523.96 2840,895.83 2810,865.83 2609.76,865.83 2609.76,570.63 2730,450.39 2730,59.03 2666.8,-4.17 1726.84,-4.17 1600.31,-4.17 1540,56.13 1540,1505.64
GND_4 on Bottom Layer "BOTTOM_LAYER_GND_4_P050" (solid, remove dead copper, pour order 50): 1565.23,4803.15 2757.87,4803.15 2811.02,4750 2811.02,4128.35 2781.02,4098.35 2580.79,4098.35 2580.79,3803.15 2701.02,3682.91 2701.02,3292.74 2636.63,3228.35 1697.87,3228.35 1572.68,3228.35 1511.02,3290 1511.02,4748.94
GND_11 on Bottom Layer "BOTTOM_LAYER_GND_11_P038" (solid, remove dead copper, pour order 38): 0,4380 2.17,4382.17 1478.19,4382.17 1478.19,3520 0,3520
GND_8 on Bottom Layer "BOTTOM_LAYER_GND_8_P028" (solid, remove dead copper, pour order 28): 0,2795.83 0.3,2796.12 1401.57,2796.12 1401.57,1990.55 1396.85,1985.83 0,1985.83
GND_7 on Bottom Layer "BOTTOM_LAYER_GND_7_P022" (solid, remove dead copper, pour order 22): 1140,598.84 1088.44,547.28 1088.44,267.41 986.86,165.83 677.95,165.83 530,313.78 530,500 378.26,651.74 338.26,651.74 320,670 320,843.78 0,843.78 0,896.18 0,1580 5.2,1574.8 1500,1574.8 1500,598.84
GND_3 on Bottom Layer "BOTTOM_LAYER_GND_3_P020" (solid, remove dead copper, pour order 20): 1624.05,3201.37 2769.81,3201.37 2840,3131.18 2840,2526.56 2810,2496.56 2609.76,2496.56 2609.76,2201.37 2730,2081.13 2730,1687.26 2669.3,1626.56 1726.84,1626.56 1610.3,1626.56 1540,1696.86 1540,3117.32
GND_1 on Bottom Layer "BOTTOM_LAYER_GND_1_P014" (solid, remove dead copper, pour order 14): 1604.99,1570.63 2793.33,1570.63 2840,1523.96 2840,895.83 2810,865.83 2609.76,865.83 2609.76,570.63 2730,450.39 2730,59.03 2666.8,-4.17 1726.84,-4.17 1597.82,-4.17 1540,53.65 1540,1505.64

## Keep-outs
Keep-Out Layer:
  text ".Layer_Name" at 577,-858.49 h60

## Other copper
Top Layer:
  text ".Layer_Name" at 577,-858.49 h60
Bottom Layer:
  text ".Layer_Name" at 577,-858.49 h60

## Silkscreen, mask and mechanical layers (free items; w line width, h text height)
Top Overlay:
  text "'.PRJ_Number'.PCB_Rev" at 1062.99,4606.3 h108.27
  text "'.PRJ_Number'.PCB_Rev" at 1062.99,2992.13 h108.27
  text "'.PRJ_Number'.PCB_Rev" at 1062.99,1377.95 h108.27
  text ".Layer_Name" at 577,-858.49 h60
Bottom Overlay:
  text ".Layer_Name" at 577,-858.49 h60
Top Paste:
  text ".Layer_Name" at 577,-858.49 h60
Bottom Paste:
  text ".Layer_Name" at 577,-858.49 h60
Top Solder:
  text ".Layer_Name" at 577,-858.49 h60
  text ".Layer_Name" at 577,-858.49 h60
Bottom Solder:
  text ".Layer_Name" at 577,-858.49 h60
Drill Guide:
  text ".Layer_Name" at 577,-858.49 h60
M1 Board Outline:
  lines w10: 0,1614.17 0,1615.83 1.65,1614.17 3149.61,1614.17 ; 0,3230 0,3188.98 ; 0,1574.8 0,3188.98 ; 0,1574.8 0,0 3149.61,0 3149.61,1574.8 ; 0,1574.8 3149.61,1574.8 ; 0,3188.98 3149.61,3188.98 ; 3149.61,1574.8 3149.61,3188.98 ; 3149.61,3188.98 3149.61,3228.35 ; 3149.61,3228.35 3149.61,4803.15 0,4803.15 0,3228.35 0,3229.09 0.75,3228.35 3149.61,3228.35
  text ".Layer_Name" at 577,-858.49 h60
M2 Board Dimensions:
  rectangle: 0,-275 125,-150
  rectangle: 125,-400 500,-275
  lines w7: 0,-275 1000,-275 ; 125,-400 125,-150 ; 250,-400 250,-150 ; 500,-400 500,-150 ; 750,-400 750,-150 ; 0,-400 1000,-400 1000,-150 0,-150 0,-400
  text ".Layer_Name" at 577,-858.49 h60
M3 3D STEP Top:
  text ".Layer_Name" at 577,-858.49 h60
M4 3D STEP Bottom:
  text ".Layer_Name" at 577,-858.49 h60
M5 Assembly Top:
  lines w10: -292,-930.17 6308,-930.17 ; -292,-726.83 6310,-726.83 ; -292,-523.5 -292,-1133.5 3713,-1133.5 6310,-1133.5 6310,-523.5 -291.5,-523.5 -291.5,-1133.5 1284,-1133.5 ; 2173,-1133.5 2173,-523.5 ; 3440,-726.83 3440,-523.5 ; 4280,-726.83 4280,-523.5 ; 4902,-1140 4902,-937.17
  text "COMPONENTS MARKED 'DNP' SHOULD NOT BE POPULATED." at 1153.5,-318.5 h60
  text "ASSEMBLY VARIANT:" at 1153,-434 h60
  text ".VariantName" at 2189,-434 h60
  text "PCB VIEWED FROM TOP SIDE" at -228.5,-655.67 h60
  text "BOARD #:" at 2248,-655.67 h60
  text ".PRJ_Number" at 2793.5,-655.67 h60
  text "REV:" at 3638,-655.67 h60
  text ".PCB_Rev" at 3929.5,-655.67 h60
  text "SVN REV:" at 4476,-655.67 h60
  text ".VersionControl_RevNumber" at 4982,-655.67 h60
  text "TID #:" at 2248,-859 h60
  text ".TID" at 2793.5,-859 h60
  text "PLOT NAME =" at -228.5,-1064.34 h60
  text ".plot_File_Name" at 577,-1064.34 h60
  text "GENERATED    :" at 2250,-1064.34 h60
  text ".Print_Date" at 3119.5,-1064.34 h60
  text ".Print_Time" at 3848.5,-1064.34 h60
  text "TEXAS INSTRUMENTS" at 5113,-1064.34 h60
M6 Assembly Bottom:
  lines w10: -292.5,-727.33 6309.5,-727.33 ; -290.5,-930.67 6309.5,-930.67 ; 1115.5,-1140.5 1115.5,-937.67 ; 1737.5,-727.33 1737.5,-524 ; 2577.5,-727.33 2577.5,-524 ; 3844.5,-1134 3844.5,-524 ; 4733.5,-1134 6309,-1134 6309,-524 -292.5,-524 -292.5,-1134 2304.5,-1134 6309.5,-1134 6309.5,-524
  text "COMPONENTS MARKED 'DNP' SHOULD NOT BE POPULATED." at 6102,-318 h60
  text ".VariantName" at 5058,-434 h60
  text "ASSEMBLY VARIANT:" at 6097,-434 h60
  text ".VersionControl_RevNumber" at 1035.5,-656.17 h60
  text "SVN REV:" at 1541.5,-656.17 h60
  text ".PCB_Rev" at 2088,-656.17 h60
  text "REV:" at 2379.5,-656.17 h60
  text ".PRJ_Number" at 3224,-656.17 h60
  text "BOARD #:" at 3769.5,-656.17 h60
  text "PCB VIEWED FROM BOTTOM SIDE" at 6246,-656.17 h60
  text ".TID" at 3224,-859.5 h60
  text "TID #:" at 3769.5,-859.5 h60
  text "TEXAS INSTRUMENTS" at 904.5,-1064.84 h60
  text ".Print_Time" at 2169,-1064.84 h60
  text ".Print_Date" at 2898,-1064.84 h60
  text "GENERATED    :" at 3767.5,-1064.84 h60
  text ".plot_File_Name" at 5440.5,-1064.84 h60
  text "PLOT NAME =" at 6246,-1064.84 h60
M9 Title Sheet:
  drawing of 57 lines, arcs and shapes, not listed
  text "1" at 739.84,8036.5 h70
  text "2" at 3235.5,8036.5 h70
  text "3" at 5724.84,8036.5 h70
  text "4" at 8231.51,8036.5 h70
  text "5" at 10730.5,8036.5 h70
  text "6" at 13235.5,8036.5 h70
  text "A" at -416.5,6893.5 h70
  text "A" at 14383.5,6893.5 h70
  text "B" at 14383.5,4513.5 h70
  text "B" at -416.5,2899.33 h70
  text "C" at 14383.5,2138.5 h70
  text "C" at -416.5,524.33 h70
  text "PROJECT TITLE:" at 11343.5,277.5 h45
  text ".PRJ_Title" at 11393.5,144.17 h70
  text "DESIGNED FOR:" at 11343.5,-23.5 h45
  text ".PRJ_Customer" at 11393.5,-163.5 h70
  text "D" at -416.5,-231.5 h70
  text "D" at 14383.5,-231.5 h70
  text "FILE NAME:" at 11343.5,-323.5 h45
  text ".PCB_File_Name_No_Path" at 11393.5,-443.5 h70
  text "Texas Instruments (TI) and/or its licensors do not warrant the accuracy or completeness of this specification" at 6374,-605.34 h45
  text "ENGINEER:" at 11343.5,-613.5 h45
  text "LAYOUT BY:" at 12848.5,-613.5 h45
  text "or any information contained therein. TI and/or its licensors do not warrant that this design will meet" at 6329.01,-718 h45
  text ".PRJ_Engineer" at 11393.5,-768.49 h70
  text ".PCB_Layout" at 12899,-768.49 h70
  text "the specifications, will be suitable for your application or fit for any particular purpose, or will operate in" at 6329.01,-830.67 h45
  text ".Layer_Name" at 577,-858.49 h60
  text "ALTIUM DESIGNER VERSION:" at 12848.5,-923.5 h45
  text "an implementation. TI and/or its licensors do not warrant that the design is production worthy. You should" at 6329.01,-943.33 h45
  text "completely validate and test your design implementation to confirm the system functionality for your application." at 6374,-1056 h45
  text ".print_Scale" at 11393.5,-1056.83 h70
  text ".Application_BuildNumber" at 12899,-1056.83 h70
  text "1" at 739.84,-1263.5 h70
  text "2" at 3235.5,-1263.5 h70
  text "3" at 5724.84,-1263.5 h70
  text "4" at 8231.51,-1263.5 h70
  text "5" at 10730.5,-1263.5 h70
  text "6" at 13235.5,-1263.5 h70
M10 Fab Notes:
  drawing of 189 lines, arcs and shapes, not listed
  text "DESIGN INFORMATION" at 12382.02,6356.17 h60
  text "MIN. TRACK WIDTH:" at 11737.46,6224.05 h60
  text "6" at 12833.7,6224.05 h60
  text "MIL" at 12988.46,6224.05 h60
  text "MIN. CLEARANCE:" at 11737.46,6099.92 h60
  text "0.15" at 12773.7,6099.93 h60
  text "mm" at 12988.46,6099.92 h60
  text "MIN. VIA PAD SIZE:" at 11737.46,5975.8 h60
  text "24" at 12803.71,5975.8 h60
  text "MIL" at 12988.46,5975.8 h60
  text "0.05mm (2MIL)" at 12432.46,5845.9 h60
  text "MINIMUM ANNULAR RING" at 11408.23,5837.67 h60
  text "EXTERNAL" at 13140.46,5837.67 h60
  text "PER" at 11608.23,5727.55 h60
  text "IPC-D-275 CLASS 2 LEVEL C" at 11828.23,5727.54 h60
  text "MIL, HOLES" at 13316.46,5627.07 h60
  text "+/-" at 12924,5618.48 h60
  text "+/-" at 13778,5618.48 h60
  text "REGISTRATION TOLERANCES:" at 11408.23,5617.42 h60
  text "METAL" at 12608,5617.42 h60
  text "5" at 13184.2,5617.42 h60
  text "3" at 14017.2,5617.42 h60
  text "MIL" at 14133.46,5617.42 h60
  text "HOLE SIZE TOLERANCE (UNLESS OTHERWISE SPECIFIED):" at 11408.23,5519.1 h60
  text "+/-" at 13778,5516.23 h60
  text "3" at 14017.2,5515.17 h60
  text "MIL" at 14133.46,5515.17 h60
  text "MATERIAL:" at 11333.46,5377.52 h60
  text "FR-4 High Tg" at 12319.9,5249 h60
  text "X" at 12175.46,5241.01 h60
  text "FR-408" at 11754.46,5236.49 h60
  text "OTHER" at 13242.46,5236.49 h60
  text "62 MIL (1.6mm) +/-10%" at 12074.56,5093.46 h60
  text "X" at 11954.46,5091.01 h60
  text "THICKNESS:" at 11408.23,5085.24 h60
  text "OTHER" at 13359.46,5085.24 h60
  text "TOLERANCE:" at 11408.23,4946.92 h60
  text "X" at 12256.46,4946.92 h60
  text "ANSI IPC-6012 TYPE 3 CLASS 2" at 12434.48,4946.92 h60
  text "OTHER +/-" at 12434.46,4802.73 h60
  text "BOW & TWIST:" at 11408.23,4657.54 h60
  text "X" at 12256.46,4657.54 h60
  text "ANSI IPC-6012 TYPE 3 CLASS 2" at 12434.48,4657.54 h60
  text "OTHER +/-" at 12434.46,4510.85 h60
  text "DRILLING:" at 11333.46,4380.23 h60
  text "NC_DRILL FILES" at 13094.46,4275.04 h60
  text "REFERENCE:" at 11408.23,4271.1 h60
  text "X" at 12065.46,4271.01 h60
  text "AS SHOWN" at 12243.46,4271.1 h60
  text "X" at 12966.46,4271.1 h60
  text "OTHER" at 13392.46,4128.85 h60
  text "PTH COPPER THICKNESS:" at 11407.91,4125.32 h60
  text "X" at 12547.14,4125.32 h60
  text "20-30 um" at 12675.14,4125.32 h60
  text "BOARD FINISH:" at 11333.46,3977.73 h60
  text "SILKSCREEN:" at 11488.68,3867.6 h60
  text "X" at 12446.46,3867.6 h60
  text "TOP" at 12563.46,3867.6 h60
  text "X" at 12956.46,3867.6 h60
  text "BOTTOM" at 13074.46,3867.6 h60
  text "SILKSCREEN COLOR:" at 11488.68,3712.41 h60
  text "X" at 12445.46,3712.41 h60
  text "WHITE" at 12563.46,3712.41 h60
  text "OTHER" at 13074.46,3712.41 h60
  text "X" at 12576.46,3568.96 h60
  text "GREEN" at 12694.46,3568.96 h60
  text "OTHER" at 13312.46,3568.96 h60
  text "SOLDER RESIST COLOR:" at 11488.68,3562.1 h60
  text "X" at 12576.46,3414.71 h60
  text "MATTE" at 12694.46,3414.71 h60
  text "SEMI-GLOSS" at 13312,3414.07 h60
  text "IMMERSION GOLD (ENIG)" at 12394.46,3241.94 h60
  text "ENEPIG" at 13732,3234.72 h60
  text "SURFACE FINISH:" at 11333.46,3233.72 h60
  text "X" at 12216.46,3233.72 h60
  text "IMM. TIN/SILVER OR EQUIV" at 11663,3096.4 h60
  text "OTHER" at 13094.46,3092.47 h60
  text "ARRAY/PANEL:" at 11333.46,2937.09 h60
  text "CUT AND TRIM PER M1 BOARD OUTLINE" at 12394.46,2928.87 h60
  text "N.C. ROUTE" at 12394.46,2792.9 h60
  text "X" at 13082.46,2792.9 h60
  text "V. SCORE" at 13260.46,2792.9 h60
  text "CERTIFICATION:" at 11333.46,2663.77 h60
  text "MATERIALS AND WORKMANSHIP FOR ALL PCBS" at 12058.46,2663.77 h60
  text "TO MEET OR EXCEED THE REQUIREMENTS OF:" at 12058.46,2569.71 h60
  text "X" at 11695.97,2441.08 h60
  text "ANSI IPC-A-600F CLASS ->" at 11823.96,2441.08 h60
  text "X" at 13471.97,2441.08 h60
  text "2" at 13581.96,2441.08 h60
  text "1" at 13266.96,2439.58 h60
  text "3" at 13935.96,2439.58 h60
  text "X" at 12507.97,2293.39 h60
  text "RoHS" at 12635.96,2293.39 h60
  text "OTHER" at 13280.36,2293.39 h60
  text "PER ORDER" at 13677.42,2293.39 h60
  text "ALL BOARDS MUST MEET OR EXCEED UL94-V0 REQUIREMENTS." at 11361,2139.57 h60
  text "PCB MUST BEAR THE UL94V-0 UL REGISTERED MATERIAL ID NUMBER" at 11361,2023.5 h60
  text "ADDITIONAL REQUIREMENTS:" at 11333.46,1854.08 h60
  text "MICROSECTION:" at 11408.23,1746.95 h60
  text "YES" at 12313.96,1746.95 h60
  text "REQUIRED" at 13175.46,1602.62 h60
  text "BARE BOARD ELEC. TEST:" at 11408.23,1599.76 h60
  text "NONE" at 12713.96,1599.76 h60
  text "PER ORDER" at 13767.46,1599.76 h60
  text "XX MIL VIAS REQUIRE NON-CONDUCTIVE FILL AND PLANARIZE" at 11576.38,1394.82 h59
  text "XX MIL VIAS REQUIRE CONDUCTIVE FILL AND PLANARIZE" at 11584.38,1290.84 h60
  text "OUTER XX MIL TRACES REQUIRE 50 OHM SINGLE-ENDED IMPEDANCE" at 11583.39,1127.46 h58
  text "LAYER 2 & 3 (INNER LAYERS) XX MIL WIDE, XX MIL SPACE / TRACES REQUIRE 100 OHM DIFFERENTIAL IMPEDANCE" at 11575.39,891.74 h60
  text ".Layer_Name" at 577,-858.49 h60
M11 Gerber Information:
  lines w10: -292,-930.17 6308,-930.17 ; -292,-726.83 6310,-726.83 ; -292,-523.5 -292,-1133.5 3713,-1133.5 6310,-1133.5 6310,-523.5 -291.5,-523.5 -291.5,-1133.5 1284,-1133.5 ; 2173,-1133.5 2173,-523.5 ; 3440,-726.83 3440,-523.5 ; 4280,-726.83 4280,-523.5 ; 4902,-1140 4902,-937.17
  text "ALL ARTWORK VIEWED FROM TOP SIDE" at -228.5,-655.67 h60
  text "BOARD #:" at 2248,-655.67 h60
  text ".PRJ_Number" at 2793.5,-655.67 h60
  text "REV:" at 3638,-655.67 h60
  text ".PCB_Rev" at 3929.5,-655.67 h60
  text "SVN REV:" at 4476,-655.67 h60
  text ".VersionControl_RevNumber" at 4982,-655.67 h60
  text "LAYER NAME =" at -228.5,-858.49 h60
  text "TID #:" at 2248,-859 h60
  text ".TID" at 2793.5,-859 h60
  text "PLOT NAME =" at -228.5,-1064.34 h60
  text ".plot_File_Name" at 577,-1064.34 h60
  text "GENERATED    :" at 2250,-1064.34 h60
  text ".Print_Date" at 3119.5,-1064.34 h60
  text ".Print_Time" at 3848.5,-1064.34 h60
  text "TEXAS INSTRUMENTS" at 5113,-1064.34 h60
M12 Stackup:
  text ".Layer_Name" at 577,-858.49 h60
M13 Component Bodies Top:
  text ".Layer_Name" at 577,-858.49 h60
M14 Component Bodies Bottom:
  text ".Layer_Name" at 577,-858.49 h60
M15 Courtyards Top:
  text ".Layer_Name" at 577,-858.49 h60
M16 Courtyards Bottom:
  text ".Layer_Name" at 577,-858.49 h60
Drill Drawing:
  text ".Layer_Name" at 577,-858.49 h60
M17 Embedded Cavity:
  text ".Layer_Name" at 577,-858.49 h60
M18 Embedded Assembly:
  text ".Layer_Name" at 577,-858.49 h60
M19 Embedded Keepout:
  text ".Layer_Name" at 577,-858.49 h60
M20 V-Cut:
  lines w10: 0,1594.49 6338.58,1594.49 ; 0,3208.66 6338.58,3208.66 ; 3169.29,0 3169.29,4803.15

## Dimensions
-20,0 to -20,4803.15 on M2 Board Dimensions
0,-400 to 1000,-400 on M2 Board Dimensions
